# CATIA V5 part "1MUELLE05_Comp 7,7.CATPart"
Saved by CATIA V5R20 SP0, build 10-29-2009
Part number: 1MUELLE05_Comp 7,7
Revision: ANY
Definition: UNKNOWN
Nomenclature: 1MUELLE05_Comp 7,7
Source: Unknown
Bounding box of the stored display mesh (mm): x -4.4 to 4.4, y -4.4 to 4.4, z -0.55 to 8.249
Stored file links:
  C:\Users\Utente\Desktop\IO LAVORO\3D X SITO CF\CUMSA\3D files AE\AE 052430\1MUELLE05_Comp 7,7.CATPart
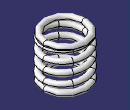
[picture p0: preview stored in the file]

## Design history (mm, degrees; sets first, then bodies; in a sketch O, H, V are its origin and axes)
Set1 "FacciaKO#NONE#20661"
  DatumSurface1 "Sup20661_1"
  Circle1 "Crv20661_1": stored without definition
Set2 "FacciaKO#NONE#11092"
  DatumSurface2 "Sup11092_1"
  Circle2 "Crv11092_1": stored without definition
Set3 "FacciaKO#NONE#8121"
  DatumSurface3 "Sup8121_1"
  Circle3 "Crv8121_1": stored without definition
Set4 "FacciaKO#NONE#20080"
  DatumSurface4 "Sup20080_1"
  Circle4 "Crv20080_1": stored without definition
Body1 "Cortar-Extruir3" (main body)
  Solid1: solid without history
